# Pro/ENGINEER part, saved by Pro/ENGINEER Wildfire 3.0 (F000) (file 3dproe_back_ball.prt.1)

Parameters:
  DESCRIPTION = "COMPRESSION RING - 10"
  MODELED_BY = "L. CONARD"
  PTC_COMMON_NAME = "COMPRESSION RING - 10"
